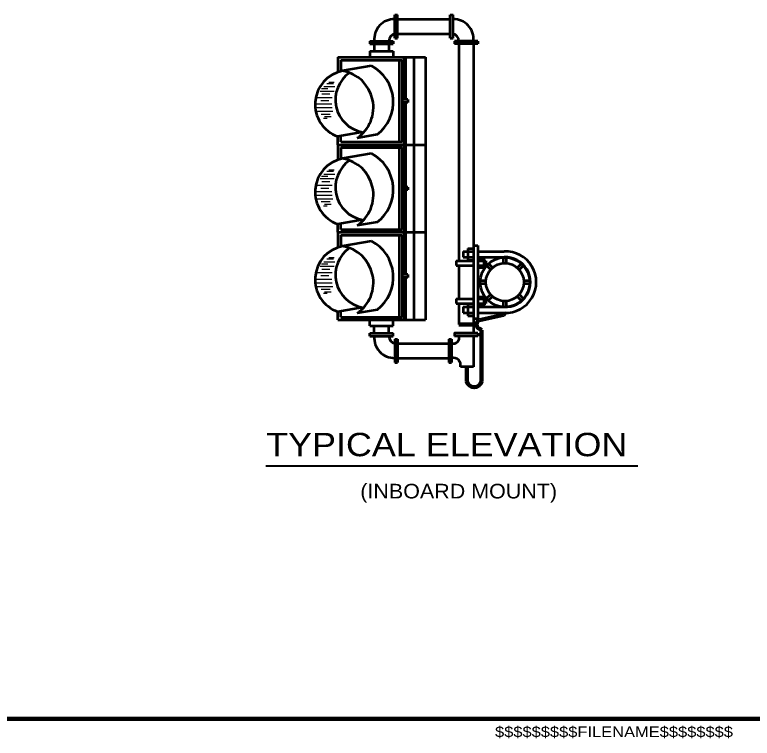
# Model space of a CAD drawing. Extents: x -370 to 486, y -203 to 341.
# Drawn here: x 107.7 to 259.3, y -195.2 to -46.5 of the extents above; entities that cross this region are included whole.
import ezdxf
from ezdxf.enums import TextEntityAlignment as Align

# ---------------------------------------------------------------- set-up
doc = ezdxf.new("R2010")
doc.units = 0
doc.header["$LTSCALE"] = 0.96
doc.layers.add('1', color=7, linetype='Continuous', lineweight=53)

msp = doc.modelspace()

# ---------------------------------------------------------------- linework, layer by layer
at = {"layer": '1'}
for p, q in [((185.7912, -51.3342), (185.7912, -46.5342)), ((185.7912, -46.5342), (186.3912, -46.5342)), ((186.3912, -51.3342), (186.3912, -46.5342)), ((197.1912, -51.3342), (197.1912, -46.5342)), ((197.1912, -51.3342), (197.1912, -46.5342)), ((197.1912, -46.5342), (197.7912, -46.5342)), ((197.7912, -51.3342), (197.7912, -46.5342)), ((186.3912, -47.4342), (197.1912, -47.4342)), ((185.7912, -51.3342), (186.3912, -51.3342)), ((186.3912, -50.4342), (197.1912, -50.4342)), ((197.1912, -51.3342), (197.7912, -51.3342)), ((180.6912, -51.9342), (185.4912, -51.9342)), ((180.6912, -51.9342), (180.6912, -52.5342)), ((180.6912, -52.5342), (185.4912, -52.5342)), ((181.5912, -52.5342), (181.5912, -54.0342)), ((184.5912, -52.5342), (184.5912, -54.0342)), ((185.4912, -51.9342), (185.4912, -52.5342)), ((202.8912, -51.9342), (198.0912, -51.9342)), ((198.0912, -51.9342), (198.0912, -52.5342)), ((202.8912, -52.5342), (198.0912, -52.5342)), ((198.9912, -52.5342), (198.9912, -97.082)), ((201.9912, -52.5342), (201.9912, -111.962)), ((202.8912, -51.9342), (202.8912, -52.5342)), ((180.6912, -54.0342), (185.4912, -54.0342)), ((180.6912, -54.0342), (180.6912, -55.2342)), ((185.4912, -54.0342), (185.4912, -55.2342)), ((174.0912, -55.2342), (192.0912, -55.2342)), ((174.0912, -55.2342), (174.0912, -58.3133)), ((174.6912, -55.8342), (187.2912, -55.8342)), ((174.6912, -55.8342), (174.6912, -58.153)), ((186.6912, -55.8342), (186.6912, -72.6342)), ((187.2912, -55.8342), (187.2912, -72.6342)), ((189.6912, -55.2342), (189.6912, -109.2342)), ((192.0912, -55.2342), (192.0912, -109.2342)), ((180.9912, -57.0342), (175.0824, -58.0761)), ((188.4912, -63.9342), (187.2912, -63.9342)), ((188.4912, -64.5342), (187.2912, -64.5342)), ((188.4912, -63.9342), (188.4912, -64.5342)), ((179.0964, -70.6569), (174.0912, -71.5394)), ((182.1912, -71.1342), (178.055, -71.8635)), ((174.0912, -73.2342), (174.0912, -71.5394)), ((174.6912, -72.6342), (174.6912, -71.4336)), ((174.6912, -72.6342), (187.2912, -72.6342)), ((174.0912, -73.2342), (192.0912, -73.2342)), ((174.0912, -73.2342), (174.0912, -76.3442)), ((174.6912, -73.8342), (187.2912, -73.8342)), ((174.6912, -73.8342), (174.6912, -76.1633)), ((186.6912, -73.8342), (186.6912, -90.6342)), ((187.2912, -73.8342), (187.2912, -90.6342)), ((180.9912, -75.0342), (175.0824, -76.0761)), ((188.4912, -81.9342), (187.2912, -81.9342)), ((188.4912, -82.5342), (187.2912, -82.5342)), ((188.4912, -81.9342), (188.4912, -82.5342)), ((179.0964, -88.6569), (174.0912, -89.5394)), ((174.6912, -90.6342), (174.6912, -89.4336)), ((182.1912, -89.1342), (178.055, -89.8635)), ((174.0912, -91.2342), (174.0912, -89.5394)), ((174.6912, -90.6342), (187.2912, -90.6342)), ((174.0912, -91.2342), (192.0912, -91.2342)), ((174.0912, -91.2342), (174.0912, -94.3442)), ((174.6912, -91.8342), (187.2912, -91.8342)), ((174.6912, -91.8342), (174.6912, -94.1633)), ((186.6912, -91.8342), (186.6912, -108.6342)), ((187.2912, -91.8342), (187.2912, -108.6342)), ((180.9912, -93.0342), (175.0824, -94.0761)), ((201.9912, -93.962), (202.8912, -93.962)), ((202.8912, -93.962), (202.8912, -108.962)), ((199.8912, -95.162), (199.8912, -96.362)), ((199.8912, -95.162), (201.9912, -95.162)), ((200.7912, -94.562), (201.9912, -94.562)), ((200.7912, -94.562), (200.7912, -96.962)), ((202.8912, -95.162), (208.2912, -95.162)), ((199.8912, -96.362), (201.9912, -96.362)), ((200.7912, -96.962), (201.9912, -96.962)), ((202.8912, -96.362), (208.2912, -96.362)), ((202.8912, -96.662), (204.0912, -96.662)), ((204.0912, -96.662), (204.0912, -98.462)), ((208.1516, -97.5608), (208.1516, -96.3874)), ((208.7516, -97.5608), (208.7516, -96.3874)), ((198.3912, -97.082), (201.9912, -97.082)), ((198.3912, -97.082), (198.3912, -98.042)), ((198.3912, -98.042), (201.9912, -98.042)), ((198.9912, -98.042), (198.9912, -104.882)), ((202.8912, -97.082), (204.5112, -97.082)), ((202.8912, -98.042), (204.5112, -98.042)), ((202.8912, -98.462), (204.0912, -98.462)), ((204.5112, -97.082), (204.5112, -98.042)), ((205.4679, -98.9021), (204.6421, -98.0764)), ((205.8922, -98.4778), (205.0664, -97.6521)), ((210.9785, -98.4978), (211.8294, -97.6516)), ((211.4016, -98.9233), (212.2525, -98.0771)), ((188.4912, -99.9342), (187.2912, -99.9342)), ((188.4912, -99.9342), (188.4912, -100.5342)), ((188.4912, -100.5342), (187.2912, -100.5342)), ((203.3517, -101.162), (204.5248, -101.162)), ((212.3248, -101.162), (213.5515, -101.162)), ((203.3517, -101.762), (204.5248, -101.762)), ((212.3248, -101.762), (213.5515, -101.762)), ((202.8912, -104.462), (204.0912, -104.462)), ((204.0912, -104.462), (204.0912, -106.262)), ((204.5972, -104.844), (205.4479, -103.998)), ((205.0203, -105.2695), (205.871, -104.4235)), ((211.8595, -105.2919), (210.9841, -104.4168)), ((212.2836, -104.8676), (211.4082, -103.9925)), ((198.3912, -104.882), (201.9912, -104.882)), ((198.3912, -104.882), (198.3912, -105.842)), ((198.3912, -105.842), (201.9912, -105.842)), ((198.9912, -105.842), (198.9912, -110.1598)), ((200.7912, -105.962), (200.7912, -108.362)), ((200.7912, -105.962), (201.9912, -105.962)), ((202.8912, -104.882), (204.5112, -104.882)), ((202.8912, -105.842), (204.5112, -105.842)), ((204.5112, -104.882), (204.5112, -105.842)), ((208.1516, -106.5874), (208.1516, -105.3606)), ((208.7516, -106.5874), (208.7516, -105.3606)), ((179.0964, -106.6569), (174.0912, -107.5394)), ((174.0912, -109.2342), (174.0912, -107.5394)), ((174.6912, -108.6342), (174.6912, -107.4336)), ((182.1912, -107.1342), (178.055, -107.8635)), ((199.8912, -106.562), (199.8912, -107.762)), ((199.8912, -106.562), (201.9912, -106.562)), ((202.8912, -106.262), (204.0912, -106.262)), ((202.8912, -106.562), (208.2912, -106.562)), ((174.6912, -108.6342), (187.2912, -108.6342)), ((199.8912, -107.762), (201.9912, -107.762)), ((200.7912, -108.362), (201.9912, -108.362)), ((201.9912, -108.962), (202.8912, -108.962)), ((202.8912, -107.762), (208.2912, -107.762)), ((174.0912, -109.2342), (192.0912, -109.2342)), ((180.6912, -110.4594), (180.6912, -109.2594)), ((180.6912, -110.4594), (185.4912, -110.4594)), ((181.5912, -111.9594), (181.5912, -110.4594)), ((184.5912, -111.9594), (184.5912, -110.4594)), ((185.4912, -110.4594), (185.4912, -109.2594)), ((180.6912, -111.9594), (185.4912, -111.9594)), ((180.6912, -112.5594), (180.6912, -111.9594)), ((185.4912, -112.5594), (185.4912, -111.9594)), ((202.8912, -111.9626), (202.8908, -112.5625)), ((180.6912, -112.5594), (185.4912, -112.5594)), ((185.7912, -113.1594), (185.7912, -117.9594)), ((185.7912, -113.1594), (186.3912, -113.1594)), ((186.3912, -113.1594), (186.3912, -117.9594)), ((196.8908, -113.1592), (196.8908, -117.9592)), ((196.8908, -113.1592), (197.4908, -113.1592)), ((197.4908, -113.1592), (197.4908, -117.9592)), ((202.8908, -112.5625), (198.0908, -112.5592)), ((201.9908, -112.5619), (201.9866, -118.8617)), ((186.3912, -114.0594), (196.8908, -114.0594)), ((185.7912, -117.9594), (186.3912, -117.9594)), ((186.3912, -117.0594), (196.8908, -117.0594)), ((196.8908, -117.9592), (197.4908, -117.9592)), ((201.9866, -118.8617), (199.2866, -118.8617))]:
    msp.add_line(p, q, dxfattribs=at)
at = {"layer": '1', "lineweight": 90}
for p, q in [((187.8912, -55.2342), (187.8912, -63.9342)), ((187.8912, -64.5342), (187.8912, -81.9342)), ((187.8912, -82.5342), (187.8912, -99.9342)), ((187.8912, -100.5342), (187.8912, -109.2342))]:
    msp.add_line(p, q, dxfattribs=at)
at = {"layer": '1', "lineweight": 25}
for p, q in [((172.2176, -60.38), (173.3534, -60.38)), ((170.7588, -61.6933), (172.0373, -61.6933)), ((171.1964, -61.292), (173.4719, -61.292)), ((171.8164, -60.6718), (173.21, -60.6718)), ((169.8471, -63.5174), (172.9504, -63.5174)), ((170.4671, -62.204), (173.3201, -62.204)), ((170.7953, -62.7877), (172.4733, -62.7877)), ((169.8106, -64.8672), (172.8396, -64.8672)), ((170.6129, -64.1375), (172.218, -64.1375)), ((169.7012, -65.5968), (172.9107, -65.5968)), ((169.7012, -66.3629), (173.0803, -66.3629)), ((170.6998, -66.9315), (172.5149, -66.9315)), ((171.1748, -67.7631), (171.8875, -67.7631)), ((171.3827, -67.4364), (172.7242, -67.4364)), ((171.8164, -78.6718), (173.21, -78.6718)), ((172.2176, -78.38), (173.3534, -78.38)), ((170.4671, -80.204), (173.3201, -80.204)), ((170.7588, -79.6933), (172.0373, -79.6933)), ((171.1964, -79.292), (173.4719, -79.292)), ((169.8471, -81.5174), (172.9504, -81.5174)), ((170.7953, -80.7877), (172.4733, -80.7877)), ((169.8106, -82.8672), (172.8396, -82.8672)), ((170.6129, -82.1375), (172.218, -82.1375)), ((169.7012, -83.5968), (172.9107, -83.5968)), ((169.7012, -84.3629), (173.0803, -84.3629)), ((170.6998, -84.9315), (172.5149, -84.9315)), ((171.1748, -85.7631), (171.8875, -85.7631)), ((171.3827, -85.4364), (172.7242, -85.4364)), ((171.8164, -96.6718), (173.21, -96.6718)), ((172.2176, -96.38), (173.3534, -96.38)), ((170.4671, -98.204), (173.3201, -98.204)), ((170.7588, -97.6933), (172.0373, -97.6933)), ((171.1964, -97.292), (173.4719, -97.292)), ((169.8471, -99.5174), (172.9504, -99.5174)), ((170.7953, -98.7877), (172.4733, -98.7877)), ((169.8106, -100.8672), (172.8396, -100.8672)), ((170.6129, -100.1375), (172.218, -100.1375)), ((169.7012, -101.5968), (172.9107, -101.5968)), ((169.7012, -102.3629), (173.0803, -102.3629)), ((170.6998, -102.9315), (172.5149, -102.9315)), ((171.1748, -103.7631), (171.8875, -103.7631)), ((171.3827, -103.4364), (172.7242, -103.4364))]:
    msp.add_line(p, q, dxfattribs=at)
at = {"layer": '1', "lineweight": 106}
for p, q in [((203.1914, -109.2624), (208.17, -108.1819)), ((203.6366, -121.8617), (203.6366, -111.3627)), ((200.6366, -121.8617), (200.6366, -118.8617))]:
    msp.add_line(p, q, dxfattribs=at)
at = {"layer": '1', "lineweight": 158}
for p, q in [((202.5914, -110.1624), (198.9912, -110.1598)), ((479.406, -191.1602), (-312.194, -191.1602))]:
    msp.add_line(p, q, dxfattribs=at)
at = {"layer": '1', "lineweight": 40}
msp.add_line((159.3077, -139.2163), (235.7396, -139.2163), dxfattribs=at)
at = {"layer": '1'}
msp.add_lwpolyline([(202.8912, -111.9626), (198.0912, -111.9592), (198.0908, -112.5592)], dxfattribs=at)
for centre, radius in [((208.4516, -101.4874), 5.1), ((208.4248, -101.4607), 3.9)]:
    msp.add_circle(centre, radius, dxfattribs=at)
for centre, radius, start, end in [((185.714, -51.5721), 4.1387, 88.93093, 185.01894), ((197.8684, -51.5721), 4.1387, 354.98106, 91.06907), ((186.2585, -52.0381), 1.6706, 106.24508, 176.43531), ((197.3239, -52.0381), 1.6706, 3.56469, 73.75492), ((177.1112, -64.4655), 8.3832, 307.29917, 62.42986), ((176.4077, -64.9418), 6.9925, 100.9259, 250.65279), ((180.4002, -63.9848), 6.7983, 125.42652, 258.94304), ((173.8143, -65.5637), 7.5942, 303.94628, 80.38748), ((177.1112, -82.4655), 8.3832, 307.29917, 62.42986), ((176.4077, -82.9418), 6.9925, 100.9259, 250.65279), ((180.4002, -81.9848), 6.7983, 125.42652, 258.94304), ((173.8143, -83.5637), 7.5942, 303.94628, 80.38748), ((177.1112, -100.4655), 8.3832, 307.29917, 62.42986), ((176.4077, -100.9418), 6.9925, 100.9259, 250.65279), ((180.4002, -99.9848), 6.7983, 125.42652, 258.94304), ((173.8143, -101.5637), 7.5942, 303.94628, 80.38748), ((208.5844, -101.462), 6.3068, 267.33556, 92.66444), ((208.5829, -101.462), 5.1083, 266.72684, 93.27315), ((185.714, -112.9215), 4.1387, 174.98106, 271.06907), ((186.2585, -112.4555), 1.6706, 183.56469, 253.75492), ((197.8382, -112.9068), 1.2036, 253.22176, 16.76297), ((197.8426, -118.5045), 1.4875, 346.10771, 103.67892)]:
    msp.add_arc(centre, radius, start, end, dxfattribs=at)
at = {"layer": '1', "lineweight": 106}
for centre, radius, start, end in [((208.0945, -107.9327), 0.2604, 286.84777, 40.95171), ((203.5664, -110.1624), 0.975, 112.61986, 247.38013), ((203.127, -111.6381), 0.5793, 28.38312, 83.61532), ((202.1366, -121.5242), 1.5375, 192.68038, 347.31962)]:
    msp.add_arc(centre, radius, start, end, dxfattribs=at)

# ---------------------------------------------------------------- texts
at = {"layer": '1'}
for s, height, width, p in [('TYPICAL ELEVATION', 4.8, 1.15, (196.4815, -137.2354)), ('(INBOARD MOUNT)', 3, 1.1, (198.9339, -145.9104))]:
    msp.add_text(s, height=height, dxfattribs=dict(at, width=width)).set_placement(p, align=Align.CENTER)
at = {"layer": '1', "width": 1.15}
msp.add_text('$$$$$$$$$FILENAME$$$$$$$$', height=2.2, dxfattribs=at).set_placement((206.406, -194.9602))

doc.saveas('drawing.dxf')
